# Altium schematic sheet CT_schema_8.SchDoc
size 254 x 194 mm
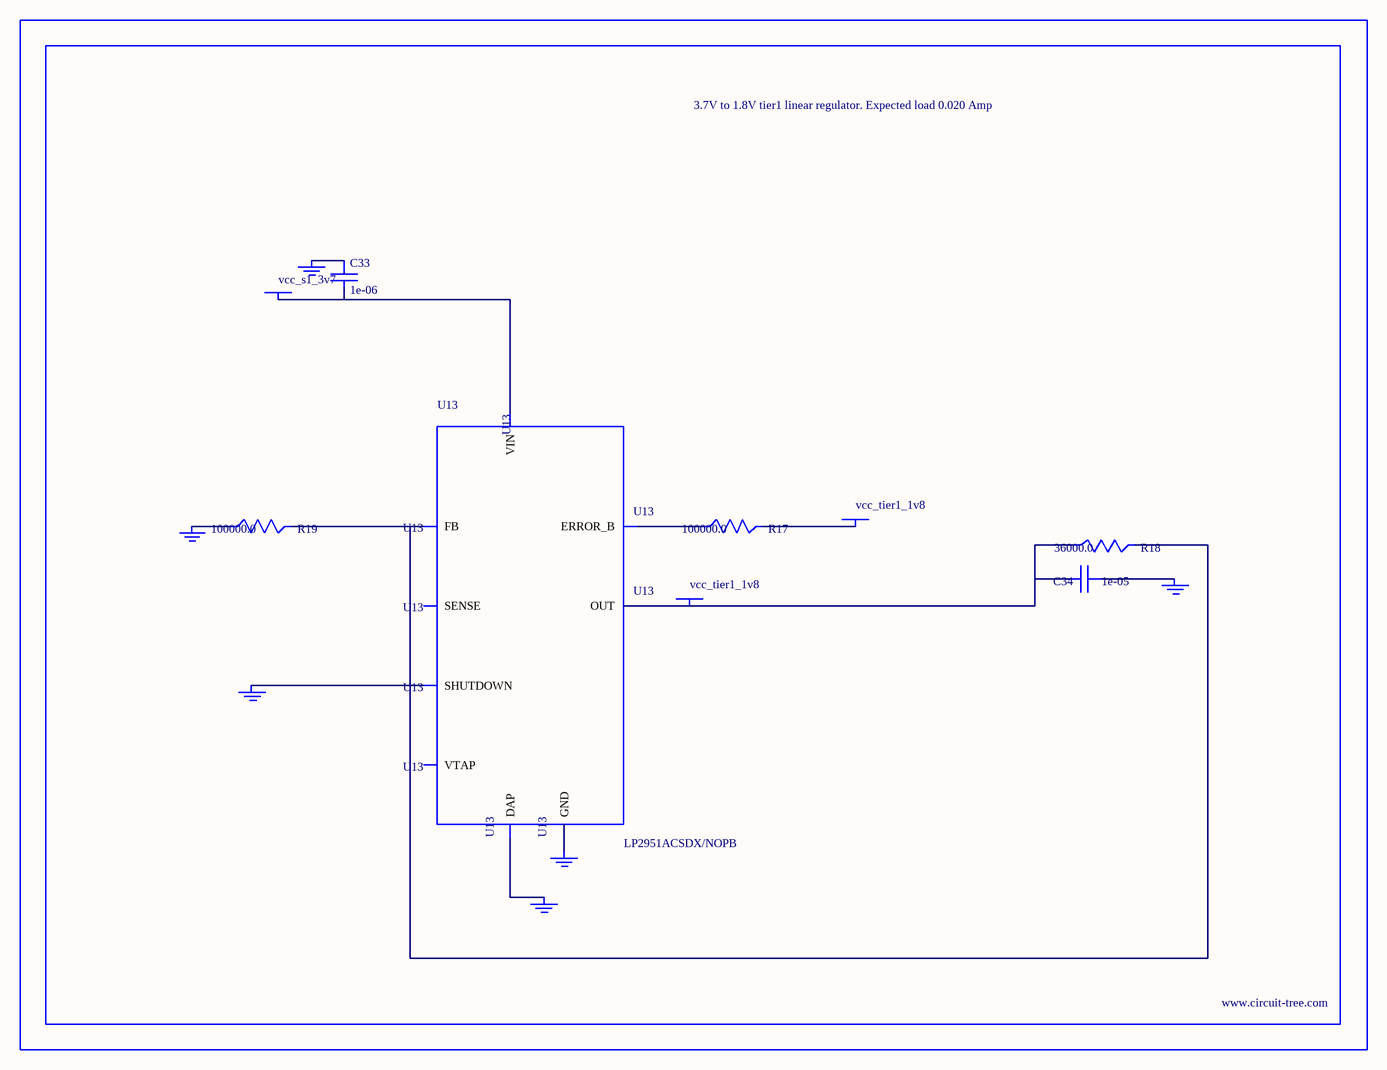
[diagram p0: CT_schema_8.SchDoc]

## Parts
BORDER7  (no value)
C33  1e-06  [C0603]
C34  1e-05  [C0805]
GND_INSTANCE_7_0  (no value)
GND_INSTANCE_7_1  (no value)
GND_INSTANCE_7_2  (no value)
GND_INSTANCE_7_3  (no value)
GND_INSTANCE_7_4  (no value)
GND_INSTANCE_7_5  (no value)
POWER_INSTANCE_7_0  vcc_tier1_1v8
POWER_INSTANCE_7_1  vcc_s1_3v7
POWER_INSTANCE_7_2  vcc_tier1_1v8
R17  100000.0  [R0603]
R18  36000.0  [R0603]
R19  100000.0  [R0603]
U13  LP2951ACSDX/NOPB  [WSON-8]

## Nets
NetC33_1: C33.1 GND_INSTANCE_7_3.0(GND)
NetC33_2: C33.2 POWER_INSTANCE_7_1.0(PWR) U13.8(VIN)
NetC34_1: C34.1 GND_INSTANCE_7_0.0(GND)
NetC34_2: C34.2 POWER_INSTANCE_7_2.0(PWR) R18.1 U13.1(OUT)
NetGND_INSTANCE_7_1_0: GND_INSTANCE_7_1.0(GND) U13.3(SHUTDOWN)
NetGND_INSTANCE_7_2_0: GND_INSTANCE_7_2.0(GND) R19.1
NetGND_INSTANCE_7_4_0: GND_INSTANCE_7_4.0(GND) U13.PAD(DAP)
NetGND_INSTANCE_7_5_0: GND_INSTANCE_7_5.0(GND) U13.4(GND)
NetPOWER_INSTANCE_7_0_0: POWER_INSTANCE_7_0.0(PWR) R17.2
NetR17_1: R17.1 U13.5(ERROR_B)
NetR18_2: R18.2 R19.2 U13.7(FB)

Not connected (* = marked no-connect by the designer): U13 2(SENSE) 6(VTAP)

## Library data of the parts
BORDER7 = BORDER_PAGE7
C33 = C0603C105K3RACTU
C34 = GRM219R60J106ME19D
GND_INSTANCE_7_0-GND_INSTANCE_7_5 = GND
POWER_INSTANCE_7_0-POWER_INSTANCE_7_2 = PWR
R17 R19 = RC0603JR-07100KL
R18 = RC0603JR-0736KL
